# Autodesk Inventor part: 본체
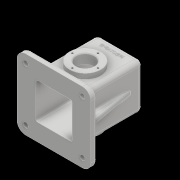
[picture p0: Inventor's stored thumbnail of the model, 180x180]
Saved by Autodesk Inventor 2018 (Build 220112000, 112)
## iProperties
Created: 2022-11
Part Number: 본체
Material: 일반
Document SubType Name: Modeling
Designer: home
Density: 1 g/cm^3
Appearance: 기본값
Author: home
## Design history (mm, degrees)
sketch "스케치1"
  geometry: L1 (50, -62)-(-50, -62); L2 (-65, -47)-(-65, 47); L3 (-50, 62)-(50, 62); L4 (65, 47)-(65, -47); L5 (65, -62)-(-65, 62); L6 (-65, -62)-(65, 62); A1 r 15 centre (50, -47) between (50, -62) and (65, -47); A2 r 15 centre (50, 47) between (65, 47) and (50, 62); A3 r 15 centre (-50, 47) between (-50, 62) and (-65, 47); A4 r 15 centre (-50, -47) between (-65, -47) and (-50, -62); 1 further point
  constraints: 12 end point, 8 point on circle, 8 point on line, 8 tangent, 4 centre point, 3 equal radius, 2 midpoint, 2 parallel, 1 horizontal, 1 perpendicular
  dimensions: "d0" = 130 distance of L5.start L6.start; "d1" = 124 distance of L6.end L5.start; "d2" = 15 radius of A1
extrude "돌출1" new body sketch "스케치1" distance "d3" = 10; taper "d4" = 0 deg
sketch "스케치2"
  geometry: C1 r 4.5 at (-50, -47); C2 r 4.5 at (-50, 47); C3 r 4.5 at (50, -47); C4 r 4.5 at (50, 47); A1 r 15 centre (-50, -47) between (-65, -47) and (-50, -62) reference; A2 r 15 centre (-50, 47) between (-50, 62) and (-65, 47) reference; A3 r 15 centre (50, -47) between (50, -62) and (65, -47) reference; A4 r 15 centre (50, 47) between (65, 47) and (50, 62) reference; 1 further point
  constraints: 4 centre point, 4 coincident
  dimensions: "d5" = 9 diameter of C1; "d6" = 9 diameter of C2; "d7" = 9 diameter of C3; "d8" = 9 diameter of C4
extrude "돌출2" cut sketch "스케치2" distance "d9" = 10; taper "d10" = 0 deg
sketch "스케치3"
  geometry: L1 (40, -40)-(-40, -40); L2 (-40, -40)-(-40, 40); L3 (-40, 40)-(40, 40); L4 (40, 40)-(40, -40); L5 (40, -40)-(-40, 40); L6 (-40, -40)-(40, 40); 1 further point
  constraints: 12 end point, 2 midpoint, 2 parallel, 1 horizontal, 1 perpendicular
  dimensions: "d11" = 80 distance of L1.end L2.end; "d12" = 80 distance of L2.end L3.end
extrude "돌출3" join sketch "스케치3" distance "d13" = 107; taper "d14" = 0 deg
sketch "스케치4"
  geometry: C1 r 20 at (0, 0); 1 further point
  constraints: 1 centre point, 1 coincident
  dimensions: "d15" = 40 diameter of C1
extrude "돌출4" join sketch "스케치4" distance "d16" = 10; taper "d17" = -10 deg
sketch "스케치5"
  geometry: 2 further points
  constraints: 1 coincident
hole "구멍1" sketch "스케치5" at (0, 0) diameter "d18" = 21; stored, may be unused: countersink angle "d22" = 90 deg, drill point angle "d24" = 0 deg; dims "d19" = 6, "d20" = 28, "d21" = 4, "d23" = 30
sketch "스케치6"
  geometry: L1 (-32, 32)-(32, 32); L2 (32, 32)-(32, -32); L3 (32, -32)-(-32, -32); L4 (-32, -32)-(-32, 32); L5 (-32, 32)-(32, -32); L6 (32, 32)-(-32, -32); 1 further point
  constraints: 12 end point, 2 midpoint, 2 parallel, 1 horizontal, 1 perpendicular
  dimensions: "d25" = 64 distance of L1.end L2.end; "d26" = 64 distance of L2.end L3.end
extrude "돌출5" cut sketch "스케치6" distance "d27" = 109; taper "d28" = 0 deg
sketch "스케치7"
  geometry: L1 (-10, -10)-(90, -10) reference; L2 (80, 0)-(80, 107) reference; C1 r 27.5 at (40, 45); 1 further point
  constraints: 1 centre point
  dimensions: "d29" = 55 diameter of C1
extrude "돌출6" join sketch "스케치7" distance "d32" = 9; taper "d33" = 0 deg
sketch "스케치8"
  geometry: C1 r 16 at (0, 0); 1 further point
  constraints: 1 centre point
  dimensions: "d34" = 32 diameter of C1
extrude "돌출7" cut sketch "스케치8" distance "d35" = 20; taper "d36" = 0 deg
node "작업 평면2"
sketch "스케치10"
  geometry: 2 further points
hole "구멍2" sketch "스케치10" at (0, 22.5) diameter "d52" = 3.242; stored, may be unused: countersink angle "d56" = 90 deg, drill point angle "d58" = 118 deg; dims "d53" = 8, "d54" = 28, "d55" = 4, "d57" = 10
chamfer "모따기1" distance "d71" = 1; stored, may be unused: second distance "d72" = 2, angle "d73" = 45 deg
chamfer "모따기2" distance "d74" = 1; stored, may be unused: second distance "d75" = 2, angle "d76" = 45 deg
fillet "모깎기10" dims "d77" = 3
fillet "모깎기11" dims "d78" = 3
fillet "모깎기12" dims "d83" = 3
fillet "모깎기17" dims "d88" = 8
fillet "모깎기19" dims "d90" = 8
node "작업 평면4"
sketch "스케치17"
  geometry: L1 (-55, 10)-(-40, 95.069); L2 (-65, 0)-(-65, 7) reference; L3 (-62, 10)-(-74.429, 10); L4 (-65, 7)-(-65, 26.325); L5 (-65, 10)-(-55, 10); L6 (-40, 10)-(-40, 109) reference; L7 (-40, 109)-(-40, 10) reference; A1 r 3 centre (-62, 7) between (-62, 10) and (-65, 7) reference; 1 further point
  constraints: 8 end point, 4 point on line, 1 tangent, 1 vertical
  dimensions: "d99" = 10 distance of L5.start L5.end; "d100" = 100 deg angle of L1 L5
feature "리브2" sketch "스케치17" dims "d101" = 1, "d102" = 10, "d103" = 0, "d104" = 0, "d105" = 1, "d106" = 1
fillet "모깎기20" dims "d107" = 3
fillet "모깎기21" dims "d108" = 3
fillet "모깎기22" dims "d109" = 3
fillet "모깎기23" dims "d110" = 3
sketch "스케치18"
  geometry: L1 (72, -96)-(72, 0) reference; L2 (13.763, 18)-(50.237, 18) reference; 2 further points
  constraints: 1 other
  dimensions: "d111" = 40 distance from line of L1 point (32, -7); "d112" = 25 distance from line of L2 point (32, -7)
feature "엠보싱3" sketch "스케치18" dims "d0" = 130, "d1" = 124, "d2" = 15, "d113" = 0.5, "d114" = 0
node "솔리드1"
mirror "미러1"
pattern_circular "원형 패턴1" dims angle "d60" = 360 deg
mirror "미러3"
mirror "미러4"
node "투영된 루프1"
other parameters: "d37" = 0, "d97" = 0
